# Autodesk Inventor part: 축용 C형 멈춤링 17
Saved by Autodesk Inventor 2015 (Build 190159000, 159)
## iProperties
Created: 2026-05
Part Number: 축용 C형 멈춤링 17
Material: 일반
Document SubType Name: Modeling
Designer: 104
Density: 1 g/cm^3
Appearance: 기본값
Author: 104
Author: jhkim
Description: 리테이닝 링(C형)
Creation Date: 2026-04-27
Sending System: Autodesk Inventor 2027
Preprocessor: ST-DEVELOPER v20.1
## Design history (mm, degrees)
node "축용 C형 멈춤링 171"
body "Solid1"
node "기준1"
